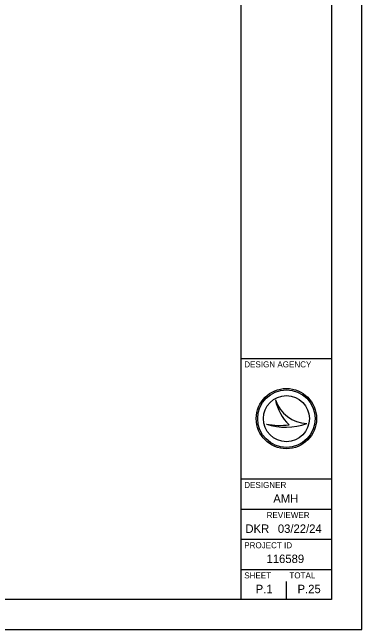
# Model space of a CAD drawing. Extents: x 0 to 34, y 0 to 22.
# Drawn here: x 28.2 to 34, y 0 to 10.24 of the extents above; entities that cross this region are included whole.
import ezdxf

# ---------------------------------------------------------------- set-up
doc = ezdxf.new("R2010")
doc.units = 0
for name, color, linetype in [('SH_Border', 7, 'Continuous'), ('SH_Cut_Line', 7, 'Continuous'), ('SH_Data', 7, 'Continuous')]:
    doc.layers.add(name, color=color, linetype=linetype)

msp = doc.modelspace()

# ---------------------------------------------------------------- linework, layer by layer
at = {"layer": 'SH_Border'}
for p, q in [((32, 0.5), (32, 21.5)), ((32, 4.5), (33.5, 4.5)), ((32, 2.5), (33.5, 2.5)), ((32, 2), (33.5, 2)), ((32, 1.5), (33.5, 1.5)), ((32, 1), (33.5, 1))]:
    msp.add_line(p, q, dxfattribs=at)
msp.add_lwpolyline([(1.5, 21.5), (33.5, 21.5), (33.5, 0.5), (1.5, 0.5)], close=True, dxfattribs=at)
at = {"layer": 'SH_Cut_Line'}
msp.add_lwpolyline([(0, 0), (34, 0), (34, 22), (0, 22)], close=True, dxfattribs=at)
at = {"layer": 'SH_Data'}
for p, q in [((32.567, 3.81), (32.567, 3.81)), ((32.75, 3.5), (32.75, 3.5)), ((32.417, 3.41), (32.417, 3.41)), ((33.087, 3.419), (33.087, 3.419)), ((32.75, 0.5), (32.75, 0.8)), ((32.375, 0.675), (32.375, 0.675))]:
    msp.add_line(p, q, dxfattribs=at)
for radius in [0.5, 0.477, 0.477, 0.382]:
    msp.add_circle((32.75, 3.5), radius, dxfattribs=at)
for centre, radius, start, end in [((33.116, 3.998), 0.58, 198.9257, 198.9319), ((33.347, 3.97), 0.796, 191.6379, 191.6421), ((33.116, 3.998), 0.58, 198.9319, 267.1657), ((33.347, 3.97), 0.796, 191.6421, 226.0947), ((32.739, 4.37), 1.013, 251.4576, 290.0832), ((32.648, 4.654), 1.266, 259.4964, 259.4995), ((32.739, 4.37), 1.013, 251.4527, 251.4576), ((32.648, 4.654), 1.266, 259.4995, 276.6672)]:
    msp.add_arc(centre, radius, start, end, dxfattribs=at)

# ---------------------------------------------------------------- texts
for s, height, p in [('DESIGN AGENCY', 0.1, (32.05, 4.35)), ('DESIGNER', 0.1, (32.05, 2.35)), ('AMH', 0.14, (32.532, 2.105)), ('REVIEWER', 0.1, (32.422, 1.85)), ('DKR', 0.14, (32.069, 1.605)), ('03/22/24', 0.14, (32.608, 1.605)), ('PROJECT ID', 0.1, (32.05, 1.35)), ('116589', 0.14, (32.42, 1.105)), ('SHEET', 0.1, (32.05, 0.85)), ('TOTAL', 0.1, (32.8, 0.85)), ('P.1', 0.14, (32.24, 0.605)), ('P.25', 0.14, (32.935, 0.605))]:
    msp.add_text(s, height=height, dxfattribs=at).set_placement(p)

doc.saveas('drawing.dxf')
